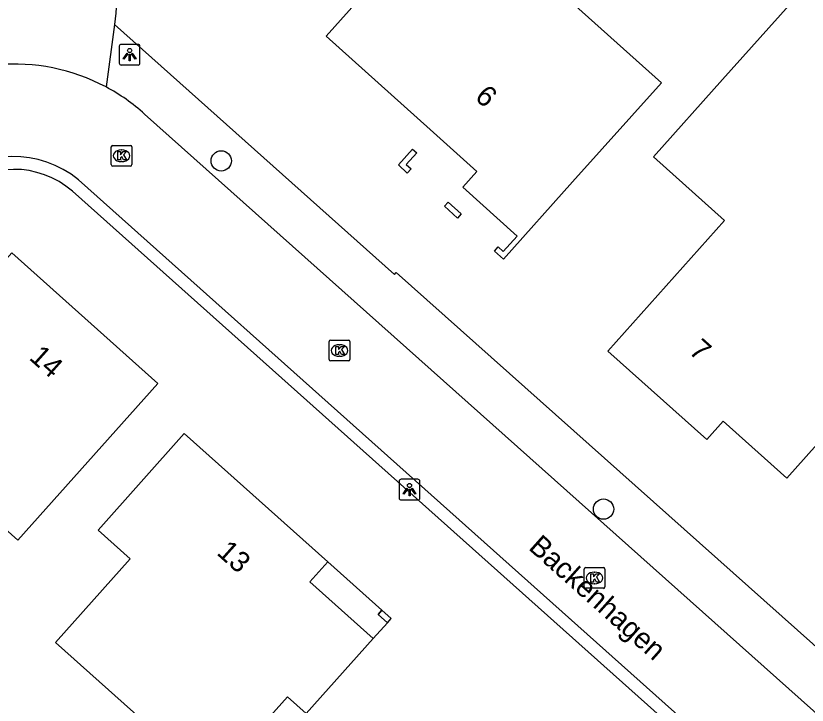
# Model space of a CAD drawing. Extents: x 157663 to 158496, y 379212 to 380934.
# Drawn here: x 158404.8 to 158442.96, y 380278.93 to 380312.16 of the extents above; entities that cross this region are included whole.
import ezdxf

# ---------------------------------------------------------------- set-up
doc = ezdxf.new("R2010")
doc.units = 0
for name, color, linetype in [('IMGEO_Boom', 7, 'Continuous'), ('IMGEO_Kolk', 7, 'Continuous'), ('IMGEO_Lichtpunt', 7, 'Continuous'), ('IMGEO_Openbare_ruimte_label', 7, 'Continuous'), ('IMGEO_Pand', 7, 'Continuous'), ('IMGEO_Pand_nummerreeks', 7, 'Continuous'), ('IMGEO_Pand_overbouw', 7, 'Continuous'), ('IMGEO_Rijbaan_lokaal_open', 7, 'Continuous'), ('IMGEO_Voetpad_open', 7, 'Continuous')]:
    doc.layers.add(name, color=color, linetype=linetype)

msp = doc.modelspace()

# ---------------------------------------------------------------- linework, layer by layer
at = {"layer": 'IMGEO_Boom'}
for centre in [(158414.701, 380305.164), (158433.136, 380288.381)]:
    msp.add_circle(centre, 0.489, dxfattribs=at)
at = {"layer": 'IMGEO_Kolk'}
for p, q in [((158409.395, 380304.986), (158409.395, 380305.838)), ((158409.47, 380305.912), (158410.322, 380305.912)), ((158410.396, 380305.838), (158410.396, 380304.986)), ((158409.883, 380305.692), (158409.908, 380305.692)), ((158409.906, 380305.132), (158409.881, 380305.132)), ((158410.322, 380304.912), (158409.47, 380304.912)), ((158419.906, 380295.6), (158419.906, 380296.452)), ((158419.981, 380296.526), (158420.833, 380296.526)), ((158420.394, 380296.306), (158420.419, 380296.306)), ((158420.907, 380296.452), (158420.907, 380295.6)), ((158420.833, 380295.526), (158419.981, 380295.526)), ((158420.417, 380295.746), (158420.392, 380295.746)), ((158432.201, 380284.637), (158432.201, 380285.489)), ((158432.276, 380285.563), (158433.128, 380285.563)), ((158433.202, 380285.489), (158433.202, 380284.637)), ((158432.689, 380285.343), (158432.714, 380285.343)), ((158432.712, 380284.783), (158432.687, 380284.783)), ((158433.128, 380284.563), (158432.276, 380284.563))]:
    msp.add_line(p, q, dxfattribs=at)
for points in [[(158409.395, 380304.986), (158409.395, 380305.838)], [(158409.47, 380305.912), (158410.322, 380305.912)], [(158410.396, 380305.838), (158410.396, 380304.986)], [(158409.716, 380305.612), (158409.839, 380305.612), (158409.839, 380305.461), (158409.969, 380305.612), (158410.133, 380305.612), (158409.987, 380305.461), (158410.14, 380305.212), (158409.988, 380305.212), (158409.903, 380305.376), (158409.839, 380305.309), (158409.839, 380305.212), (158409.716, 380305.212), (158409.716, 380305.612)], [(158410.322, 380304.912), (158409.47, 380304.912)], [(158419.906, 380295.6), (158419.906, 380296.452)], [(158419.981, 380296.526), (158420.833, 380296.526)], [(158420.227, 380296.226), (158420.35, 380296.226), (158420.35, 380296.075), (158420.48, 380296.226), (158420.644, 380296.226), (158420.498, 380296.075), (158420.651, 380295.826), (158420.499, 380295.826), (158420.414, 380295.99), (158420.35, 380295.923), (158420.35, 380295.826), (158420.227, 380295.826), (158420.227, 380296.226)], [(158420.907, 380296.452), (158420.907, 380295.6)], [(158420.833, 380295.526), (158419.981, 380295.526)], [(158432.201, 380284.637), (158432.201, 380285.489)], [(158432.276, 380285.563), (158433.128, 380285.563)], [(158433.202, 380285.489), (158433.202, 380284.637)], [(158432.522, 380285.263), (158432.645, 380285.263), (158432.645, 380285.112), (158432.775, 380285.263), (158432.939, 380285.263), (158432.793, 380285.112), (158432.946, 380284.863), (158432.794, 380284.863), (158432.709, 380285.027), (158432.645, 380284.96), (158432.645, 380284.863), (158432.522, 380284.863), (158432.522, 380285.263)], [(158433.128, 380284.563), (158432.276, 380284.563)]]:
    msp.add_lwpolyline(points, dxfattribs=at)
for centre, start, end in [((158409.472, 380305.836), 91.552, 178.448), ((158409.472, 380305.836), 91.552, 178.448), ((158410.32, 380305.836), 1.552, 88.448), ((158410.32, 380305.836), 1.552, 88.448), ((158409.472, 380304.988), 181.552, 268.448), ((158409.472, 380304.988), 181.552, 268.448), ((158410.32, 380304.988), 271.552, 358.448), ((158410.32, 380304.988), 271.552, 358.448), ((158419.983, 380296.45), 91.552, 178.448), ((158419.983, 380296.45), 91.552, 178.448), ((158420.831, 380296.45), 1.552, 88.448), ((158420.831, 380296.45), 1.552, 88.448), ((158419.983, 380295.602), 181.552, 268.448), ((158419.983, 380295.602), 181.552, 268.448), ((158420.831, 380295.602), 271.552, 358.448), ((158420.831, 380295.602), 271.552, 358.448), ((158432.278, 380285.487), 91.552, 178.448), ((158432.278, 380285.487), 91.552, 178.448), ((158433.126, 380285.487), 1.552, 88.448), ((158433.126, 380285.487), 1.552, 88.448), ((158432.278, 380284.639), 181.552, 268.448), ((158432.278, 380284.639), 181.552, 268.448), ((158433.126, 380284.639), 271.552, 358.448), ((158433.126, 380284.639), 271.552, 358.448)]:
    msp.add_arc(centre, 0.0765, start, end, dxfattribs=at)
for centre, major_axis, ratio, start_param, end_param in [((158409.882, 380305.412), (-0.387, 0.002), 0.722429, 4.712389, 7.853982), ((158409.907, 380305.412), (-0.39, 0.002), 0.717154, 1.570796, 4.712389), ((158420.393, 380296.026), (-0.387, 0.002), 0.722429, 4.712389, 7.853982), ((158420.418, 380296.026), (-0.39, 0.002), 0.717154, 1.570796, 4.712389), ((158432.688, 380285.063), (-0.387, 0.002), 0.722429, 4.712389, 7.853982), ((158432.713, 380285.063), (-0.39, 0.002), 0.717154, 1.570796, 4.712389)]:
    msp.add_ellipse(centre, major_axis=major_axis, ratio=ratio, start_param=start_param, end_param=end_param, dxfattribs=at)
at = {"layer": 'IMGEO_Lichtpunt'}
for p, q in [((158409.786, 380310.688), (158409.786, 380309.881)), ((158409.786, 380310.688), (158409.786, 380309.881)), ((158410.688, 380310.783), (158409.88, 380310.783)), ((158410.688, 380310.783), (158409.88, 380310.783)), ((158410.782, 380309.881), (158410.782, 380310.688)), ((158410.782, 380309.881), (158410.782, 380310.688)), ((158409.88, 380309.787), (158410.688, 380309.787)), ((158409.88, 380309.787), (158410.688, 380309.787)), ((158423.281, 380289.723), (158423.281, 380288.916)), ((158423.281, 380289.723), (158423.281, 380288.916)), ((158424.183, 380289.818), (158423.375, 380289.818)), ((158424.183, 380289.818), (158423.375, 380289.818)), ((158424.277, 380288.916), (158424.277, 380289.723)), ((158424.277, 380288.916), (158424.277, 380289.723)), ((158423.375, 380288.822), (158424.183, 380288.822)), ((158423.375, 380288.822), (158424.183, 380288.822))]:
    msp.add_line(p, q, dxfattribs=at)
for points in [[(158410.16, 380310.352), (158410.199, 380310.324), (158410.011, 380310.062), (158409.973, 380310.089), (158410.16, 380310.352)], [(158410.262, 380310.304), (158410.309, 380310.304), (158410.309, 380309.982), (158410.262, 380309.982), (158410.262, 380310.304)], [(158410.372, 380310.324), (158410.41, 380310.351), (158410.597, 380310.089), (158410.558, 380310.061), (158410.372, 380310.324)], [(158423.655, 380289.387), (158423.694, 380289.359), (158423.506, 380289.097), (158423.468, 380289.124), (158423.655, 380289.387)], [(158423.757, 380289.339), (158423.804, 380289.339), (158423.804, 380289.017), (158423.757, 380289.017), (158423.757, 380289.339)], [(158423.867, 380289.359), (158423.905, 380289.386), (158424.092, 380289.124), (158424.053, 380289.096), (158423.867, 380289.359)]]:
    msp.add_lwpolyline(points, dxfattribs=at)
for centre in [(158410.285, 380310.486), (158423.78, 380289.521)]:
    msp.add_circle(centre, 0.0994, dxfattribs=at)
for centre, start, end in [((158409.88, 380310.688), 90, 180), ((158409.88, 380310.688), 90, 180), ((158410.688, 380310.688), 0, 90), ((158410.688, 380310.688), 0, 90), ((158409.88, 380309.881), 180, 270), ((158409.88, 380309.881), 180, 270), ((158410.688, 380309.881), 270, 0), ((158410.688, 380309.881), 270, 360), ((158423.375, 380289.723), 90, 180), ((158423.375, 380289.723), 90, 180), ((158424.183, 380289.723), 0, 90), ((158424.183, 380289.723), 0, 90), ((158423.375, 380288.916), 180, 270), ((158423.375, 380288.916), 180, 270), ((158424.183, 380288.916), 270, 0), ((158424.183, 380288.916), 270, 360)]:
    msp.add_arc(centre, 0.0946, start, end, dxfattribs=at)
at = {"layer": 'IMGEO_Pand'}
for points in [[(158431.644, 380304.153), (158428.306, 380300.43), (158427.876, 380300.815), (158428.058, 380301.018), (158428.302, 380300.798), (158428.968, 380301.54), (158426.346, 380303.896), (158427.024, 380304.652), (158424.776, 380306.68), (158419.756, 380311.18), (158423.094, 380314.903), (158425.845, 380317.972), (158435.928, 380308.932), (158431.644, 380304.153)], [(158445.302, 380293.598), (158441.969, 380289.87), (158438.9, 380292.614), (158438.115, 380291.736), (158433.344, 380296.001), (158438.969, 380302.293), (158435.538, 380305.361), (158438.871, 380309.089), (158443.904, 380314.718), (158449.078, 380310.092), (158444.955, 380305.481), (158451.053, 380300.03), (158445.302, 380293.598)], [(158423.674, 380304.581), (158423.242, 380304.969), (158423.93, 380305.736), (158424.132, 380305.556), (158423.625, 380304.99), (158423.855, 380304.783), (158423.674, 380304.581)], [(158426.094, 380302.412), (158425.462, 380302.98), (158425.643, 380303.182), (158426.276, 380302.615), (158426.094, 380302.412)], [(158404.89, 380286.877), (158411.647, 380294.436), (158404.602, 380300.734), (158402.983, 380298.922), (158400.72, 380300.945), (158394.735, 380294.251), (158397.192, 380292.054), (158398.039, 380293.002), (158404.89, 380286.877)], [(158422.031, 380282.141), (158418.975, 380284.874), (158419.836, 380285.836), (158412.917, 380292.022), (158408.761, 380287.374), (158410.312, 380285.987), (158406.707, 380281.954), (158414.228, 380275.23), (158417.897, 380279.333), (158418.799, 380278.526), (158422.031, 380282.141)], [(158422.445, 380283.504), (158422.266, 380283.303), (158422.713, 380282.903), (158422.892, 380283.104), (158422.445, 380283.504)]]:
    msp.add_lwpolyline(points, dxfattribs=at)
at = {"layer": 'IMGEO_Pand_overbouw'}
msp.add_lwpolyline([(158422.445, 380283.504), (158419.836, 380285.836), (158418.975, 380284.874), (158422.031, 380282.141), (158422.713, 380282.903), (158422.266, 380283.303)], close=True, dxfattribs=at)
at = {"layer": 'IMGEO_Rijbaan_lokaal_open'}
for points in [[(158411.004, 380307.423), (158458.282, 380265.269), (158455.226, 380261.928)], [(158455.226, 380261.928), (158407.817, 380304.245)]]:
    msp.add_lwpolyline(points, dxfattribs=at)
for centre, radius, start, end in [((158404.731, 380300.462), 9.37, 61.8906, 128.2068), ((158404.782, 380300.533), 9.284, 47.9158, 61.9595), ((158404.696, 380300.515), 4.863, 50.0723, 132.1001)]:
    msp.add_arc(centre, radius, start, end, dxfattribs=at)
at = {"layer": 'IMGEO_Voetpad_open'}
for points in [[(158409.562, 380311.734), (158409.146, 380308.727)], [(158409.562, 380311.734), (158423.061, 380299.687), (158423.144, 380299.783), (158443.237, 380281.884), (158451.713, 380274.144)], [(158407.523, 380303.702), (158454.843, 380261.446), (158454.886, 380261.5)]]:
    msp.add_lwpolyline(points, dxfattribs=at)
for centre, radius, start, end in [((158395.922, 380313.62), 13.77, 352.1295, 28.6051), ((158404.704, 380300.467), 4.291, 48.9303, 131.5752)]:
    msp.add_arc(centre, radius, start, end, dxfattribs=at)

# ---------------------------------------------------------------- texts
at = {"layer": 'IMGEO_Openbare_ruimte_label'}
msp.add_text('Backenhagen', height=1, rotation=318.2428, dxfattribs=at).set_placement((158429.473, 380286.473))
at = {"layer": 'IMGEO_Pand_nummerreeks'}
for s, rotation, p in [('6', 317.9453, (158426.882, 380308.174)), ('7', 318.2051, (158437.204, 380295.931)), ('14', 318.2043, (158405.391, 380295.63)), ('13', 318.2014, (158414.439, 380286.225))]:
    msp.add_text(s, height=1, rotation=rotation, dxfattribs=at).set_placement(p)

doc.saveas('drawing.dxf')
